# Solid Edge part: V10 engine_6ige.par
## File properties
Author: KULL
Template: Iso Metric Part.par
Last saved by: KULL
Revision: 72
Application: Solid Edge
Density: 6920,000 kg/m^3
Accuracy: 0,990
Material: Iron, grey cast type 60
Face Style: Gray
Fill Style: ANSI31(Iron)
Virtual Style: ANSI31(Iron)
Categorization: Metals\Iron
LibraryName: Materials
Coef. of Thermal Exp: 1.1e-05
Thermal Conductivity: 48.0
Specific Heat: 544.0
Modulus of Elasticity: 158579411000.0
Poisson's Ratio: 0.29
Yield Stress: 275790291.72673446
Ultimate Stress: 413685437.59010166
Elongation: 0.0
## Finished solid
Body 1: sheet body, 1 face, 42 edges, 42 vertices.
  Faces by surface: plane 1
  Edges by curve: line 36, circle 6
Body 2: sheet body, 3 faces, 42 edges, 42 vertices.
  Faces by surface: plane 3
  Edges by curve: line 38, circle 4
Body 3: sheet body, 1 face, 12 edges, 12 vertices.
  Faces by surface: plane 1
  Edges by curve: line 7, circle 5
Body 4: sheet body, 1 face, 12 edges, 12 vertices.
  Faces by surface: plane 1
  Edges by curve: line 7, circle 5
Body 5: sheet body, 1 face, 12 edges, 12 vertices.
  Faces by surface: plane 1
  Edges by curve: line 7, circle 5
Body 6: sheet body, 1 face, 12 edges, 12 vertices.
  Faces by surface: plane 1
  Edges by curve: line 7, circle 5
Body 7: solid body, 152 faces, 394 edges, 236 vertices.
  Faces by surface: plane 96, cylinder 40, torus 16
  Edges by curve: line 286, circle 108
Bounding box of the edges (mm; curved faces can reach further): 102.794 x 75.076 x 42.986, from (-51.3987, -39.4607, 37.9906) to (51.3957, 35.6155, 80.9761).
Cylindrical faces by radius (mm): R3 x2, R4 x4, R6 x10, R8 x2, R9 x20, R9.5 x2
Toroidal faces (ring radius, tube radius in mm): R7 r1 x10, R8.2 r0.2 x2, R9.3 r0.2 x2, R11.5 r2 x2
Planar faces by outward normal: +x 11, +z 3, -x 11, -z 17, oblique 54
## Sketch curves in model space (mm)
line (48, 16.5423, 30.5002) -> (48, -16.5423, 30.5002)
line (48, -16.5423, 30.5002) -> (48, 16.5423, 30.5002)
circle centre (48, 0, 38.6638) radius 9.5
circle centre (48, 0, 38.6638) radius 8
circle centre (48, 0, 38.6638) radius 15.3056
line (48, -15.1609, 77.7496) -> (48, -12.5898, 74.6854)
line (48, -12.5898, 74.6854) -> (48, 12.5898, 74.6854)
line (48, 15.1609, 77.7496) -> (48, 12.5898, 74.6854)
line (48, 15.1609, 77.7496) -> (48, 35.6155, 60.5862)
line (48, 35.6155, 60.5862) -> (48, 20.5423, 42.6226)
line (48, 20.5423, 42.6226) -> (48, 20.5423, 26.5002)
line (48, 20.5423, 26.5002) -> (48, -20.5423, 26.5002)
line (48, -20.5423, 26.5002) -> (48, -20.5423, 42.6226)
line (48, -20.5423, 42.6226) -> (48, -35.6155, 60.5862)
line (48, -35.6155, 60.5862) -> (48, -15.1609, 77.7496)
line (48, 16.5423, 44.0785) -> (48, 16.5423, 30.5002)
line (48, 29.9802, 60.0931) -> (48, 16.5423, 44.0785)
line (48, 15.654, 72.1143) -> (48, 29.9802, 60.0931)
line (48, 14.455, 70.6854) -> (48, 15.654, 72.1143)
line (48, -14.455, 70.6854) -> (48, 14.455, 70.6854)
line (48, -15.654, 72.1143) -> (48, -14.455, 70.6854)
line (48, -16.5423, 30.5002) -> (48, -16.5423, 44.0785)
line (48, -16.5423, 44.0785) -> (48, -29.9802, 60.0931)
line (48, -29.9802, 60.0931) -> (48, -15.654, 72.1143)
line (48, 15.9009, 66.6854) -> (48, 24.3449, 59.6001)
line (48, 24.3449, 59.6001) -> (48, 12.5423, 45.5344)
line (48, 12.5423, 45.5344) -> (48, 12.5423, 34.5002)
line (48, 12.5423, 34.5002) -> (48, -12.5423, 34.5002)
line (48, -12.5423, 34.5002) -> (48, -12.5423, 45.5344)
line (48, -12.5423, 45.5344) -> (48, -24.3449, 59.6001)
line (48, -24.3449, 59.6001) -> (48, -15.9009, 66.6854)
line (48, -15.9009, 66.6854) -> (48, 15.9009, 66.6854)
line (48, 33.0444, 57.522) -> (-48, 33.0444, 57.522)
line (-48, 33.0444, 57.522) -> (-48, 12.5898, 74.6854)
line (-48, 12.5898, 74.6854) -> (48, 12.5898, 74.6854)
line (48, 12.5898, 74.6854) -> (48, 33.0444, 57.522)
line (48, -12.5898, 74.6854) -> (48, -33.0444, 57.522)
line (48, -33.0444, 57.522) -> (-48, -33.0444, 57.522)
line (-48, -33.0444, 57.522) -> (-48, -12.5898, 74.6854)
line (-48, -12.5898, 74.6854) -> (48, -12.5898, 74.6854)
line (0, -20.5423, 42.6226) -> (0, -20.5423, 37.4805)
line (0, -21.5469, 43.8199) -> (0, -20.5423, 42.6226)
line (0, -20.5423, 37.4805) -> (0, -18.158, 22.4349)
line (0, 20.5423, 42.6226) -> (0, 20.5423, 37.4805)
line (0, 21.5469, 43.8199) -> (0, 20.5423, 42.6226)
line (0, 20.5423, 37.4805) -> (0, 18.158, 22.4349)
line (0, -20.5423, 42.6226) -> (0, -20.5423, 37.4805)
line (0, -21.5469, 43.8199) -> (0, -20.5423, 42.6226)
line (0, -20.5423, 37.4805) -> (0, -18.158, 22.4349)
line (0, 20.5423, 42.6226) -> (0, 20.5423, 37.4805)
line (0, 21.5469, 43.8199) -> (0, 20.5423, 42.6226)
line (0, 20.5423, 37.4805) -> (0, 18.158, 22.4349)
line (0, -17.9423, 25.0349) -> (0, -12.1902, 25.0349)
line (0, -17.9423, 46.8445) -> (0, -17.9423, 25.0349)
line (0, -15.9159, 48.5449) -> (0, -17.9423, 46.8445)
line (0, -15.9159, 48.5449) -> (0, -12.1902, 25.0349)
line (0, 17.9423, 25.0349) -> (0, 12.1902, 25.0349)
line (0, 17.9423, 46.8445) -> (0, 17.9423, 25.0349)
line (0, 15.9159, 48.5449) -> (0, 17.9423, 46.8445)
line (0, -17.9423, 25.0349) -> (0, -12.1902, 25.0349)
line (0, -17.9423, 46.8445) -> (0, -17.9423, 25.0349)
line (0, -15.9159, 48.5449) -> (0, -17.9423, 46.8445)
line (0, 17.9423, 25.0349) -> (0, 12.1902, 25.0349)
line (0, 17.9423, 46.8445) -> (0, 17.9423, 25.0349)
line (0, 15.9159, 48.5449) -> (0, 17.9423, 46.8445)
line (0, 15.9159, 48.5449) -> (0, 12.1902, 25.0349)
line (0, -1.6194, 61.6114) -> (0, 1.6194, 61.6114)
line (0, -12.5898, 74.6854) -> (0, -1.6194, 61.6114)
line (0, -12.5898, 74.6854) -> (0, 12.5898, 74.6854)
circle centre (0, 0, 38.6638) radius 4
line (0, -41.2162, 67.2608) -> (0, -20.5423, 42.6226)
line (0, -41.2162, 67.2608) -> (0, -20.7617, 84.4243)
line (0, -20.7617, 84.4243) -> (0, -12.5898, 74.6854)
line (0, -21.5469, 43.8199) -> (0, -23.6514, 42.054)
line (0, -18.158, 22.4349) -> (0, -20.5423, 22.4349)
line (0, -20.5423, 22.4349) -> (0, -23.6514, 42.054)
line (0, 21.5469, 43.8199) -> (0, 23.6514, 42.054)
line (0, 18.158, 22.4349) -> (0, 20.5423, 22.4349)
line (0, 20.5423, 22.4349) -> (0, 23.6514, 42.054)
line (0, 10.4081, 72.0854) -> (0, 12.5898, 74.6854)
line (0, 1.6194, 61.6114) -> (0, 10.4081, 72.0854)
line (0, -10.9191, 72.6944) -> (0, -1.6194, 61.6114)
line (0, -1.6194, 61.6114) -> (0, -2.7629, 61.6114)
line (0, -2.7629, 61.6114) -> (0, -11.5902, 72.1314)
line (0, -11.5902, 72.1314) -> (0, -10.9191, 72.6944)
line (0, 2.7629, 61.6114) -> (0, 1.6194, 61.6114)
line (0, 11.5902, 72.1314) -> (0, 2.7629, 61.6114)
line (0, 1.6194, 61.6114) -> (0, 10.9191, 72.6944)
line (0, 10.9191, 72.6944) -> (0, 11.5902, 72.1314)
line (0, 3.8574, 53.4416) -> (0, -1.9287, 55.0599)
line (0, -1.9287, 55.0599) -> (0, -3.8574, 53.4416)
line (0, -3.8574, 53.4416) -> (0, 3.8574, 53.4416)
line (0, 2.0773, 61.6114) -> (0, -2.0773, 61.6114)
line (0, -2.0773, 61.6114) -> (0, 0, 59.1358)
line (0, 0, 59.1358) -> (0, 2.0773, 61.6114)
line (0, 0, 82.3136) -> (0, 39.108, 82.3136)
line (0, 39.108, 82.3136) -> (0, 39.108, 23.2994)
line (0, 39.108, 23.2994) -> (0, 0, 23.2994)
line (0, 0, 23.2994) -> (0, 0, 82.3136)
line (0, 0, 81.7842) -> (0, -39.844, 81.7842)
line (0, -39.844, 81.7842) -> (0, -39.844, 0)
line (0, -39.844, 0) -> (0, 0, 0)
line (0, 0, 0) -> (0, 0, 81.7842)
line (0, 41.2162, 67.2608) -> (0, 20.5423, 42.6226)
line (0, 41.2162, 67.2608) -> (0, 20.7617, 84.4243)
line (0, 20.7617, 84.4243) -> (0, 12.5898, 74.6854)
line (0, 20.5423, 42.6226) -> (0, 20.5423, 26.5002)
line (0, 20.5423, 26.5002) -> (0, 0, 26.5002)
line (0, -20.5423, 26.5002) -> (0, 0, 26.5002)
line (0, -20.5423, 42.6226) -> (0, -20.5423, 26.5002)
line (0, 12.5898, 74.6854) -> (0, 0, 74.6854)
line (0, -12.5898, 74.6854) -> (0, 0, 74.6854)
arc centre (-18, -25.3882, 69.1679) radius 9 from (-10.8482, -29.5736, 65.6559) through (-18.2666, -32.2796, 63.3853) to (-25.1518, -29.5736, 65.6559)
line (-10.8482, -29.5736, 65.6559) -> (-7.1518, -29.5736, 65.6559)
arc centre (0, -25.3882, 69.1679) radius 9 from (7.1518, -29.5736, 65.6559) through (-0.2666, -32.2796, 63.3853) to (-7.1518, -29.5736, 65.6559)
line (7.1518, -29.5736, 65.6559) -> (10.8482, -29.5736, 65.6559)
arc centre (18, -25.3882, 69.1679) radius 9 from (25.1518, -29.5736, 65.6559) through (17.7334, -32.2796, 63.3853) to (10.8482, -29.5736, 65.6559)
line (25.1518, -29.5736, 65.6559) -> (28.8482, -29.5736, 65.6559)
arc centre (36, -25.3882, 69.1679) radius 9 from (42.3572, -30.2685, 65.0728) through (35.1337, -32.2506, 63.4097) to (28.8482, -29.5736, 65.6559)
line (42.3572, -39.4607, 57.3596) -> (42.3572, -30.2685, 65.0728)
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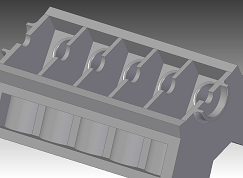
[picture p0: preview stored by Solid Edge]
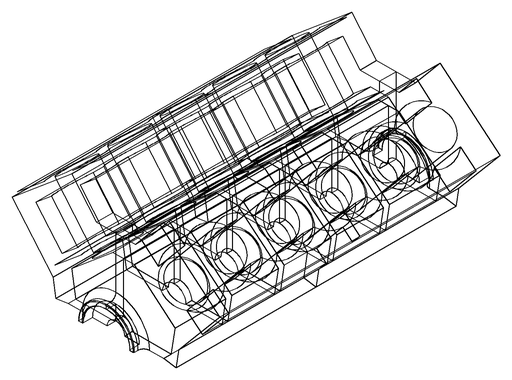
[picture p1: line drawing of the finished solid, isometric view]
